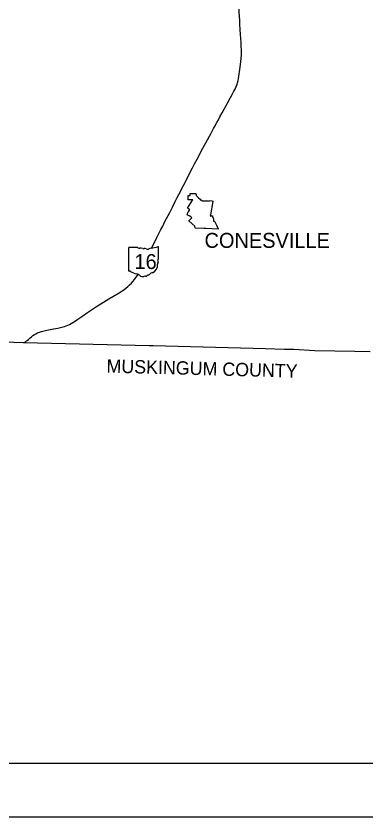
# Model space of a CAD drawing. Extents: x 1913970 to 2276415, y 78841 to 927181.
# Drawn here: x 2124487 to 2150744, y 751181 to 811241 of the extents above; entities that cross this region are included whole.
import ezdxf

# ---------------------------------------------------------------- set-up
doc = ezdxf.new("R2010")
doc.units = 0
for name, color, linetype in [('GM_X_Corporation', 7, 'Continuous'), ('GM_X_Corporation_Text', 7, 'Continuous'), ('GM_X_County', 7, 'Continuous'), ('GM_X_County_Text', 7, 'Continuous'), ('GM_X_State_Location', 7, 'Continuous'), ('GM_X_State_Shield', 7, 'Continuous'), ('SH_Border', 7, 'Continuous'), ('SH_Cut_Line', 7, 'Continuous'), ('UT_P_Electric', 7, 'Continuous')]:
    doc.layers.add(name, color=color, linetype=linetype)

msp = doc.modelspace()

# ---------------------------------------------------------------- linework, layer by layer
at = {"layer": 'GM_X_Corporation'}
msp.add_lwpolyline([(2137335, 796341), (2137347, 796404), (2137358, 796429), (2137378, 796476), (2137383, 796489), (2137415, 796556), (2137443, 796601), (2137519, 796723), (2137498, 796736), (2137358, 796821), (2137731, 797432), (2137747, 797459), (2137536, 797465), (2137398, 797468), (2137403, 797663), (2137405, 797775), (2137550, 797772), (2137559, 797934), (2137973, 797928), (2137993, 797868), (2138004, 797778), (2138004, 797776), (2138057, 797722), (2138123, 797653), (2138178, 797597), (2138298, 797503), (2138360, 797440), (2138367, 797433), (2138397, 797432), (2138490, 797373), (2138610, 797383), (2138881, 797371), (2138973, 797369), (2138979, 797405), (2139168, 797377), (2139254, 797365), (2139249, 797337), (2139247, 797327), (2139245, 797321), (2139071, 796322), (2139062, 796267), (2139234, 796259), (2139232, 796219), (2139281, 796092), (2139313, 796027), (2139300, 795858), (2139349, 795854), (2139382, 795853), (2139525, 795567), (2139650, 795287), (2139659, 795267), (2138727, 795316), (2138572, 795313), (2137922, 795345), (2137912, 795486), (2137467, 795854), (2137447, 795870), (2137464, 795888), (2137521, 795948), (2137554, 795983), (2137564, 795993), (2137653, 796088), (2137683, 796115), (2137611, 796190), (2137480, 796257)], close=True, dxfattribs=at)
at = {"layer": 'GM_X_County'}
msp.add_lwpolyline([(2151050, 786066), (2149915, 786091), (2146903, 786142), (2145320, 786224), (2144635, 786226), (2143204, 786275), (2134773, 786503), (2134471, 786517), (2125039, 786734), (2123596, 786788)], dxfattribs=at)
at = {"layer": 'GM_X_State_Shield'}
for p, q in [((2132935, 793850), (2132935, 792148)), ((2133614, 793879), (2132957, 793879)), ((2135177, 793031), (2135177, 793921)), ((2135176, 793031), (2135177, 793031))]:
    msp.add_line(p, q, dxfattribs=at)
for centre, radius, start, end in [((2132961, 793853), 26, 98.1301, 188.1301), ((2133770, 794076), 252, 231.61951, 271.11188), ((2133853, 792924), 904, 80.48669, 94.98827), ((2134059, 793862), 72.7, 219.79206, 297.10237), ((2134165, 793665), 151, 54.46668, 119.14113), ((2134360, 793935), 182, 233.85621, 294.82819), ((2134681, 793359), 478, 97.34618, 120.76885), ((2134378, 796198), 2377, 275.84447, 288.90645), ((2135152, 793925), 25, 351.86209, 97.738), ((2135171, 792966), 38.6, 107.94398, 210.33697), ((2134925, 792853), 232, 340.03296, 23.64957), ((2135150, 793028), 26.7, 289.60381, 7.73413), ((2134511, 792546), 595, 292.30889, 8.98584), ((2135266, 792659), 169, 136.8065, 186.92959), ((2132961, 792145), 26.2, 171.95839, 258.30661), ((2132965, 792319), 200, 267.33899, 280.60386), ((2133006, 792050), 72.1, 29.74838, 93.27175), ((2133916, 793579), 1716, 240.41292, 257.1985), ((2133404, 791384), 537, 47.18416, 75.83597), ((2133985, 792042), 341, 230.70037, 286.29184), ((2134182, 791454), 280, 85.69512, 111.20995), ((2134207, 791914), 182, 268.77702, 315.54927), ((2134371, 791750), 51.1, 65.75173, 132.64842), ((2134349, 791984), 192, 282.87319, 323.27711), ((2134762, 791671), 326, 94.40312, 142.57675)]:
    msp.add_arc(centre, radius, start, end, dxfattribs=at)
at = {"layer": 'SH_Border'}
msp.add_lwpolyline([(2016415, 923181), (2272415, 923181), (2272415, 755181), (2016415, 755181)], close=True, dxfattribs=at)
at = {"layer": 'SH_Cut_Line'}
msp.add_lwpolyline([(2004415, 751181), (2276415, 751181), (2276415, 927181), (2004415, 927181)], close=True, dxfattribs=at)
at = {"layer": 'UT_P_Electric'}
for points in [[(2140838, 805598), (2140918, 805750), (2140988, 805897), (2141025, 805984), (2141075, 806120), (2141112, 806237), (2141157, 806402), (2141186, 806552), (2141215, 806726), (2141278, 807231), (2141348, 807808), (2141378, 808083), (2141394, 808299), (2141399, 808560), (2141395, 808710), (2141387, 808956), (2141368, 809244), (2141353, 809549), (2141333, 809859), (2141312, 810236), (2141287, 810641), (2141271, 810900), (2141233, 811535), (2141205, 812029)], [(2135003, 794516), (2135058, 794624), (2135160, 794829), (2135363, 795226), (2135493, 795477), (2135665, 795821), (2136016, 796506), (2136217, 796906), (2136432, 797326), (2136587, 797625), (2136817, 798084), (2136925, 798298), (2137193, 798816), (2137470, 799378), (2137717, 799849), (2137876, 800154), (2138066, 800504), (2138507, 801321), (2138854, 801960), (2139011, 802242), (2139097, 802406), (2139310, 802795), (2139380, 802923), (2139565, 803261), (2139674, 803457), (2139790, 803674), (2139952, 803974), (2140108, 804268), (2140407, 804806), (2140741, 805413), (2140838, 805598)], [(2134657, 793838), (2134678, 793879), (2135003, 794516)], [(2128952, 788378), (2128956, 788381), (2129121, 788497), (2129500, 788760), (2129788, 788961), (2130218, 789261), (2130596, 789513), (2131062, 789793), (2131452, 790026), (2131758, 790212), (2132214, 790484), (2132455, 790631), (2132571, 790713), (2132731, 790829), (2132873, 790947), (2133011, 791074), (2133153, 791216), (2133254, 791329), (2133376, 791480), (2133488, 791631), (2133581, 791766), (2133642, 791866)], [(2127336, 787783), (2127618, 787837), (2127816, 787877), (2128013, 787923), (2128116, 787954), (2128248, 788000), (2128368, 788047), (2128503, 788110), (2128630, 788175), (2128753, 788248), (2128952, 788378)], [(2125041, 786731), (2125150, 786795), (2125220, 786839), (2125272, 786876), (2125332, 786921), (2125419, 786995), (2125561, 787118), (2125649, 787196), (2125754, 787284), (2125862, 787360), (2125964, 787421), (2126099, 787482), (2126246, 787529), (2126404, 787577), (2126597, 787632), (2126794, 787677), (2127056, 787729), (2127300, 787776), (2127336, 787783)]]:
    msp.add_lwpolyline(points, dxfattribs=at)

# ---------------------------------------------------------------- texts
at = {"layer": 'GM_X_Corporation_Text'}
msp.add_text('CONESVILLE', height=1120, rotation=0.00001, dxfattribs=at).set_placement((2138630, 793857))
at = {"layer": 'GM_X_County_Text'}
msp.add_text('MUSKINGUM COUNTY', height=1000, rotation=358.45973, dxfattribs=at).set_placement((2131266, 784504))
at = {"layer": 'GM_X_State_Location'}
msp.add_text('16', height=1, rotation=0.00001, dxfattribs=at).set_placement((2133789, 792579))
for s in ['s', 'r']:
    msp.add_text(s, height=1, dxfattribs=at).set_placement((2134041, 792652))
at = {"layer": 'GM_X_State_Shield'}
msp.add_text('16', height=1120.7, dxfattribs=at).set_placement((2133373, 792268))

doc.saveas('drawing.dxf')
